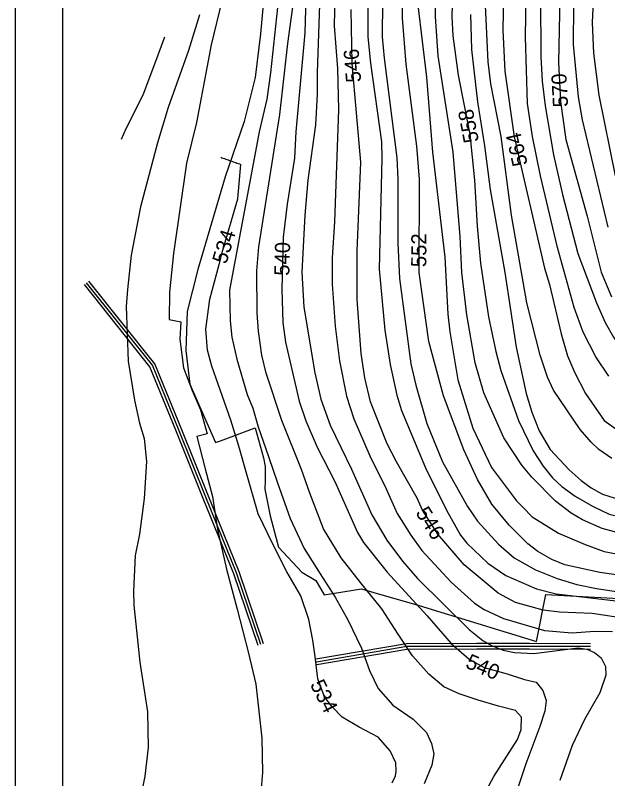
# Model space of a CAD drawing. Extents: x -709418 to -703832, y -1161719 to -1157826.
# Drawn here: x -709417.7 to -709104.5, y -1160344.3 to -1159940.7 of the extents above; entities that cross this region are included whole.
import ezdxf

# ---------------------------------------------------------------- set-up
doc = ezdxf.new("R2010")
doc.units = 0
for name, color, linetype in [('103_hranice KÚ', 7, 'Continuous'), ('120_vrstevnice hlavní', 7, 'Continuous'), ('121_vrstevnice hlavní_popis', 7, 'Continuous'), ('122_vrstevnice základní', 7, 'Continuous'), ('717_elektronická komunikace O2', 7, 'Continuous'), ('735_OP sítí TI', 7, 'Continuous'), ('800_mřížka', 7, 'Continuous')]:
    doc.layers.add(name, color=color, linetype=linetype)

msp = doc.modelspace()

# ---------------------------------------------------------------- linework, layer by layer
at = {"layer": '103_hranice KÚ'}
msp.add_lwpolyline([(-709285.11, -1159917.26), (-709288.11, -1159950.51), (-709290.92, -1159973.58), (-709296.72, -1159996.78), (-709306.78, -1160026.14), (-709321.23, -1160075.06), (-709326.78, -1160097.35), (-709327.51, -1160117.86), (-709325.42, -1160135.77), (-709311.8, -1160166.61), (-709309.19, -1160165.64), (-709290.91, -1160158.8), (-709286.51, -1160174.63), (-709285.65, -1160179.34), (-709285.72, -1160186.59), (-709285.76, -1160191.24), (-709283.04, -1160205.38), (-709278.63, -1160221.85), (-709266.19, -1160235.07), (-709258.87, -1160239.6), (-709254.37, -1160247.12), (-709234.67, -1160243.94), (-709228.11, -1160245.9), (-709204.24, -1160252.78), (-709142.18, -1160271.79), (-709137.26, -1160246.96), (-709095.28, -1160249.24)], dxfattribs=at)
at = {"layer": '120_vrstevnice hlavní'}
for points in [[(-709263.87, -1159918.8), (-709264.74, -1159950.04), (-709269.37, -1160002.4), (-709270.09, -1160016.29), (-709274, -1160040.59), (-709276.17, -1160057.95), (-709276.89, -1160085.72), (-709276.31, -1160103.08), (-709274.87, -1160113.49), (-709267.64, -1160144.73), (-709264.16, -1160155.15), (-709258.23, -1160169.03), (-709248.83, -1160187.26), (-709236.83, -1160214.16), (-709233.64, -1160219.37), (-709221.2, -1160235.14), (-709200.03, -1160258.15), (-709187.37, -1160272.88), (-709177.8, -1160281.17), (-709169.79, -1160285.55), (-709157.7, -1160288.89), (-709148.49, -1160291.82), (-709142.42, -1160293.34), (-709138.88, -1160297.65), (-709137.11, -1160302.97), (-709137.87, -1160308.54), (-709140.38, -1160316.79), (-709147.76, -1160336.46), (-709159.3, -1160370.96)], [(-709223.66, -1159933.26), (-709223.81, -1159952.07), (-709222.8, -1159963.35), (-709216, -1160016), (-709215.42, -1160027.28), (-709215.56, -1160061.13), (-709214.7, -1160079.93), (-709208.62, -1160125.06), (-709206.02, -1160136.34), (-709200.23, -1160156.59), (-709191.84, -1160176.84), (-709178.68, -1160200.42), (-709173.47, -1160208.09), (-709162.33, -1160220.38), (-709154.09, -1160227.61), (-709142.66, -1160233.98), (-709131.23, -1160238.46), (-709120.82, -1160241.65), (-709110.41, -1160243.82), (-709068.75, -1160250.18)], [(-709129.93, -1159930.95), (-709130.51, -1159965.66), (-709129.5, -1159986.2), (-709126.75, -1160006.45), (-709115.47, -1160046.96), (-709108.09, -1160076.46), (-709102.6, -1160089.48)], [(-709320.29, -1159940.5), (-709326.22, -1159959.3), (-709336.92, -1159989.39), (-709342.56, -1160008.19), (-709351.53, -1160042.04), (-709356.5, -1160067.56), (-709358.45, -1160085.64), (-709359.05, -1160094.69), (-709358.07, -1160123.55), (-709354.71, -1160144.16), (-709352.11, -1160156.31)], [(-709177.09, -1159940.21), (-709176.51, -1159958.72), (-709173.47, -1159986.49), (-709169.71, -1160009.64), (-709166.67, -1160032.78), (-709159.01, -1160076.75), (-709152.93, -1160116.09), (-709147.72, -1160140.68), (-709144.69, -1160150.52), (-709140.78, -1160160.36), (-709135, -1160170.19), (-709124.87, -1160181.04), (-709118.65, -1160186.68), (-709113.3, -1160190.59), (-709107.37, -1160193.91), (-709087.26, -1160200.28)], [(-709352.11, -1160156.31), (-709349.65, -1160164.41), (-709348.35, -1160176.56), (-709349.65, -1160196.23), (-709352.11, -1160215.03), (-709354.28, -1160226.31), (-709355.29, -1160245.12), (-709355.14, -1160252.64), (-709351.82, -1160282.73), (-709347.91, -1160309.05), (-709347.48, -1160327.85), (-709349.21, -1160342.9), (-709351.53, -1160354.18), (-709353.7, -1160361.7), (-709360.35, -1160376.74), (-709361.7, -1160379.38)]]:
    msp.add_lwpolyline(points, dxfattribs=at)
at = {"layer": '122_vrstevnice základní'}
for points in [[(-709081.48, -1160219.08), (-709107.51, -1160211.99), (-709117.93, -1160207.51), (-709123.86, -1160203.89), (-709132.1, -1160197.67), (-709144.69, -1160184.95), (-709150.04, -1160178.58), (-709159.44, -1160164.12), (-709170, -1160140.4), (-709174.63, -1160124.48), (-709179.11, -1160099.03), (-709181.72, -1160076.75), (-709182.58, -1160057.66), (-709186.2, -1160013.11), (-709194.16, -1159962.19), (-709195.6, -1159941.36), (-709195.89, -1159909.54)], [(-709186.06, -1159912.58), (-709186.92, -1159941.36), (-709186.49, -1159951.49), (-709183.6, -1159972.32), (-709177.38, -1160003.56), (-709174.92, -1160027.86), (-709173.62, -1160052.16), (-709171.88, -1160071.83), (-709167.54, -1160100.18), (-709163.78, -1160118.41), (-709161.03, -1160128.53), (-709151.77, -1160154.86), (-709143.96, -1160171.06), (-709138.76, -1160179.16), (-709133.69, -1160185.24), (-709128.78, -1160189.86), (-709121.69, -1160194.93), (-709112.58, -1160200.28), (-709103.75, -1160204.47), (-709086.4, -1160208.67), (-709059.49, -1160213.15), (-709028.54, -1160216.04)], [(-709276.98, -1159916.74), (-709282.82, -1159971.16), (-709284.7, -1159985.05), (-709288.75, -1160002.26)], [(-709103.9, -1160131.43), (-709110.84, -1160121.3), (-709117.49, -1160108.28), (-709122.27, -1160095.27), (-709131.09, -1160063.44), (-709140.06, -1160025.55), (-709144.25, -1160004.72), (-709147, -1159987.36), (-709148.01, -1159952.07), (-709147.44, -1159918.94)], [(-709111.56, -1159918.8), (-709112.86, -1159944.55), (-709112.14, -1159960.75), (-709109.25, -1159983.02), (-709100.57, -1160025.55)], [(-709256.79, -1159929.79), (-709258.23, -1159970.87), (-709258.09, -1159982.44), (-709259.1, -1159998.64), (-709263.01, -1160027.86), (-709264.74, -1160046.38), (-709266.19, -1160076.46), (-709265.18, -1160094.98), (-709259.39, -1160129.69), (-709256.21, -1160143.58), (-709251.29, -1160157.46), (-709240.01, -1160180.61), (-709229.3, -1160204.76), (-709221.35, -1160218.21), (-709213.1, -1160229.35), (-709205.15, -1160238.46), (-709177.67, -1160265.66), (-709170.58, -1160271.3), (-709165.95, -1160273.9), (-709159.88, -1160276.36), (-709153.8, -1160277.52), (-709143.68, -1160278.1), (-709120.24, -1160275.06), (-709115.61, -1160275.78), (-709111.56, -1160277.66), (-709108.09, -1160280.41), (-709105.78, -1160285.04), (-709105.63, -1160289.67), (-709108.67, -1160298.93), (-709116.77, -1160312.96), (-709123.42, -1160326.7), (-709129.79, -1160345.21)], [(-709248.83, -1159930.08), (-709249.12, -1159946.28), (-709247.39, -1159968.85), (-709246.81, -1159990.54), (-709248.97, -1160049.85), (-709250.28, -1160068.94), (-709250.28, -1160082.83), (-709248.69, -1160105.1), (-709246.37, -1160123.33), (-709242.61, -1160142.13), (-709238.85, -1160153.99), (-709230.32, -1160173.66), (-709221.64, -1160191.02), (-709215.85, -1160204.04), (-709208.62, -1160215.61), (-709202.83, -1160223.71), (-709187.36, -1160240.49), (-709174.92, -1160251.48), (-709169.85, -1160254.81), (-709159.73, -1160259.58), (-709138.03, -1160265.95), (-709123.43, -1160267.25), (-709111.56, -1160266.38), (-709102.02, -1160266.53)], [(-709231.33, -1159927.77), (-709231.33, -1159952.07), (-709229.88, -1159965.95), (-709224.1, -1160007.61), (-709223.95, -1160016.29), (-709225.4, -1160075.02), (-709222.36, -1160107.13), (-709219.61, -1160125.35), (-709216, -1160141.55), (-709213.54, -1160149.65), (-709200.81, -1160180.03), (-709189.82, -1160202.3), (-709182.44, -1160215.61), (-709179.11, -1160219.8), (-709167.97, -1160230.36), (-709158.43, -1160236.87), (-709142.23, -1160243.96), (-709131.81, -1160246.56), (-709101.73, -1160250.04), (-709068.75, -1160257.41), (-709056.6, -1160257.41), (-709049.66, -1160255.68)], [(-709087.84, -1160238.32), (-709108.67, -1160235.28), (-709127.19, -1160231.23), (-709134.13, -1160228.48), (-709141.51, -1160224.14), (-709146.86, -1160220.09), (-709156.69, -1160210.26), (-709165.81, -1160199.12), (-709173.47, -1160186.1), (-709180.7, -1160170.48), (-709191.41, -1160141.84), (-709199.07, -1160113.2), (-709204.28, -1160076.75), (-709203.99, -1160027.28), (-709205.44, -1160009.93), (-709211.08, -1159966.53), (-709213.1, -1159942.23), (-709213.1, -1159926.61)], [(-709159.73, -1159929.79), (-709160.02, -1159948.6), (-709158.86, -1159970.29), (-709154.09, -1160005.01), (-709138.03, -1160074.44), (-709135.29, -1160083.12), (-709129.21, -1160109.15), (-709125.74, -1160120.72), (-709122.12, -1160129.4), (-709116.34, -1160140.68), (-709106.36, -1160155), (-709095.36, -1160162.96), (-709090.73, -1160165.42), (-709072.59, -1160172.86), (-709059.48, -1160175.8), (-709042.42, -1160178.73), (-709025.07, -1160181.04), (-709000.77, -1160185.23), (-708931.05, -1160189.51), (-708905.01, -1160186.54), (-708889.1, -1160186.97), (-708881.87, -1160188.27)], [(-709308.43, -1159932.11), (-709314.21, -1159956.41), (-709316.53, -1159968.56), (-709321.95, -1159997.32), (-709327.13, -1160018.83), (-709334.07, -1160066.59), (-709336.19, -1160087.05), (-709336.38, -1160101.54), (-709330.24, -1160102.7), (-709330.7, -1160111.91), (-709328.75, -1160127.07), (-709324.29, -1160139), (-709319.8, -1160149.38)], [(-709177.05, -1160366.09), (-709164.79, -1160343.11), (-709152.29, -1160323.65), (-709150.26, -1160318.23), (-709150.14, -1160311.73), (-709153.22, -1160308.34), (-709162.25, -1160306), (-709172.99, -1160302.82), (-709183.04, -1160299.47), (-709191.23, -1160295.77), (-709199.14, -1160289.14), (-709207.7, -1160279.32), (-709215.41, -1160267.95), (-709223.99, -1160254.55), (-709235.21, -1160240.56), (-709245.49, -1160227.51), (-709254.76, -1160212.24), (-709261.95, -1160193.29), (-709266.48, -1160180.9), (-709276.75, -1160154.86), (-709285.14, -1160129.98), (-709287.31, -1160120.43), (-709289.19, -1160107.71), (-709289.91, -1160098.16), (-709290.06, -1160075.88), (-709289.04, -1160063.16), (-709277.9, -1159993.15), (-709273.71, -1159955.54), (-709270.53, -1159932.4)], [(-709140.06, -1159931.53), (-709139.91, -1159962.48), (-709139.19, -1159975.5), (-709137.6, -1159988.52), (-709133.26, -1160014.55), (-709128.49, -1160035.38), (-709120.39, -1160066.63), (-709110.55, -1160092.66), (-709105.92, -1160103.08), (-709101.58, -1160110.89), (-709094.21, -1160121.3), (-709085.24, -1160128.68), (-709064.41, -1160137.79), (-709050.52, -1160141.7), (-709034.32, -1160145.02), (-709008.87, -1160151.24), (-708976.47, -1160157.9), (-708957.95, -1160160.93), (-708933.07, -1160163.97), (-708916.58, -1160163.97), (-708905.88, -1160164.84), (-708878.4, -1160165.42), (-708865.38, -1160167.3)], [(-709095.36, -1160259.58), (-709112.72, -1160256.98), (-709130.08, -1160256.26), (-709138.76, -1160255.24), (-709153.22, -1160251.19), (-709162.48, -1160246.27), (-709180.41, -1160231.23), (-709194.44, -1160215.03), (-709202.4, -1160202.3), (-709205.29, -1160195.94), (-709216.29, -1160176.84), (-709221.06, -1160167.3), (-709229.88, -1160145.02), (-709232.92, -1160132.3), (-709234.95, -1160119.57), (-709236.97, -1160090.93), (-709236.97, -1160065.47), (-709235.09, -1160018.31), (-709239.57, -1159966.24), (-709240.15, -1159937.6)], [(-709204.86, -1159935.29), (-709200.38, -1159973.48), (-709197.19, -1160013.11), (-709190.68, -1160068.65), (-709189.09, -1160098.74), (-709188.08, -1160108), (-709183.74, -1160133.45), (-709175.79, -1160158.91), (-709165.95, -1160179.74), (-709152.79, -1160197.38), (-709149.46, -1160200.71), (-709144.54, -1160205.92), (-709130.51, -1160214.45), (-709116.48, -1160220.53), (-709106.36, -1160224.14), (-709084.08, -1160228.48)], [(-709102.45, -1160175.11), (-709109.25, -1160170.19), (-709113.3, -1160166.43), (-709119.09, -1160159.78), (-709133.26, -1160138.95), (-709136.3, -1160132.01), (-709140.35, -1160120.43), (-709147.29, -1160092.66), (-709155.39, -1160046.38), (-709160.89, -1160004.72), (-709166.38, -1159976.95), (-709167.83, -1159965.38), (-709169.13, -1159935.58)], [(-709122.56, -1159956.12), (-709122.41, -1159935.29)], [(-709338.76, -1159952.33), (-709344.15, -1159966.56), (-709350.37, -1159982.9), (-709359.2, -1160000.67), (-709361.7, -1160006.39)], [(-709104.33, -1160052.74), (-709117.93, -1159996.04), (-709119.95, -1159983.89), (-709122.56, -1159956.12)], [(-709288.75, -1160002.26), (-709304.4, -1160086.12), (-709304.09, -1160102.21), (-709303.22, -1160110.89), (-709300.61, -1160122.46), (-709295.12, -1160141.26), (-709292.08, -1160148.5), (-709289.33, -1160158.33), (-709283.84, -1160173.95), (-709279.06, -1160187.91), (-709272.49, -1160206.77), (-709265.09, -1160222.57), (-709256.61, -1160236.03), (-709248.55, -1160248.42), (-709242.02, -1160260.3), (-709234.64, -1160275.3), (-709230.5, -1160287.19), (-709225.85, -1160296.71), (-709218.15, -1160305.52), (-709207.46, -1160312.86), (-709200.27, -1160319.81), (-709197.69, -1160325.75), (-709196.47, -1160331.2), (-709197.46, -1160337.16), (-709201.5, -1160347.05)], [(-709316.07, -1160117.78), (-709317.08, -1160106.61), (-709314.81, -1160090.71), (-709309.9, -1160072.54), (-709308, -1160064.97), (-709300.06, -1160037.72), (-709298.54, -1160019.55)], [(-709218.53, -1160346.57), (-709216.68, -1160342.81), (-709216.35, -1160340.59), (-709216.54, -1160336), (-709219.64, -1160329.54), (-709225.98, -1160322.42), (-709235.94, -1160317.16), (-709244.99, -1160311.75), (-709250.3, -1160306.33), (-709254.32, -1160301.07), (-709257.77, -1160291.55), (-709259.19, -1160279.8), (-709260.43, -1160271.12), (-709262.48, -1160260.22), (-709266.8, -1160247.64), (-709274.19, -1160234.9), (-709281.59, -1160220.41), (-709289.33, -1160204.26), (-709295.43, -1160182.83), (-709299.6, -1160168.46), (-709303.8, -1160154.71), (-709313.81, -1160126.28), (-709316.07, -1160117.78)], [(-709319.8, -1160149.38), (-709316.21, -1160162.04), (-709321.83, -1160163.44), (-709317.31, -1160180.46), (-709313.49, -1160195.1), (-709310.79, -1160212.49), (-709306.09, -1160233.6), (-709300.36, -1160254.71), (-709294.4, -1160277.91), (-709290.56, -1160294.42), (-709288.58, -1160311.75), (-709287.33, -1160322.82), (-709287.07, -1160341.06), (-709287.87, -1160351.63)]]:
    msp.add_lwpolyline(points, dxfattribs=at)
msp.add_open_spline([(-709309.14, -1160015.76), (-709298.54, -1160019.55)], degree=1, dxfattribs=at)
at = {"layer": '717_elektronická komunikace O2'}
for points in [[(-709287.92, -1160273.43), (-709300.73, -1160235.53), (-709316.98, -1160195.55), (-709331.48, -1160159.58), (-709345.22, -1160125.74), (-709380, -1160082.18)], [(-709258.52, -1160282.49), (-709210.81, -1160274.26), (-709173.67, -1160274.2), (-709145.93, -1160274.17)], [(-709145.93, -1160274.17), (-709113.66, -1160274.28)]]:
    msp.add_lwpolyline(points, dxfattribs=at)
at = {"layer": '735_OP sítí TI'}
for points in [[(-709289.34, -1160273.91), (-709302.14, -1160236.05), (-709318.37, -1160196.11), (-709332.87, -1160160.14), (-709346.53, -1160126.51), (-709381.18, -1160083.11)], [(-709286.5, -1160272.95), (-709299.32, -1160235.01), (-709315.59, -1160194.99), (-709330.09, -1160159.02), (-709343.91, -1160124.97), (-709378.83, -1160081.24)], [(-709258.77, -1160281.02), (-709210.94, -1160272.76), (-709173.68, -1160272.7), (-709145.93, -1160272.67)], [(-709145.92, -1160272.67), (-709113.65, -1160272.78)], [(-709258.26, -1160283.97), (-709210.68, -1160275.76), (-709173.67, -1160275.7), (-709145.93, -1160275.67)], [(-709145.94, -1160275.67), (-709113.66, -1160275.78)]]:
    msp.add_lwpolyline(points, dxfattribs=at)
at = {"layer": '800_mřížka'}
for points in [[(-703832.2, -1161718.9), (-703832.2, -1157825.62), (-709417.73, -1157825.62), (-709417.73, -1161718.9)], [(-703857.2, -1161693.9), (-703857.2, -1157850.62), (-709392.73, -1157850.62), (-709392.73, -1161693.9)]]:
    msp.add_lwpolyline(points, close=True, dxfattribs=at)

# ---------------------------------------------------------------- texts
at = {"layer": '121_vrstevnice hlavní_popis'}
for s, rotation, p in [('546', 94.5516, (-709234.86, -1159975.92)), ('570', 93.1321, (-709125.47, -1159989.05)), ('558', 100.8376, (-709172.6, -1160007.32)), ('564', 102.6659, (-709146.83, -1160019.51)), ('534', 73.1734, (-709306.21, -1160072.63)), ('552', 89.656, (-709200.47, -1160073.89)), ('540', 88.4966, (-709272.87, -1160078.5)), ('546', 302.084, (-709206.38, -1160203.7)), ('540', 337.0069, (-709180.25, -1160285.4)), ('534', 296.8439, (-709262.08, -1160294.47))]:
    msp.add_text(s, height=8, rotation=rotation, dxfattribs=at).set_placement(p)

doc.saveas('drawing.dxf')
